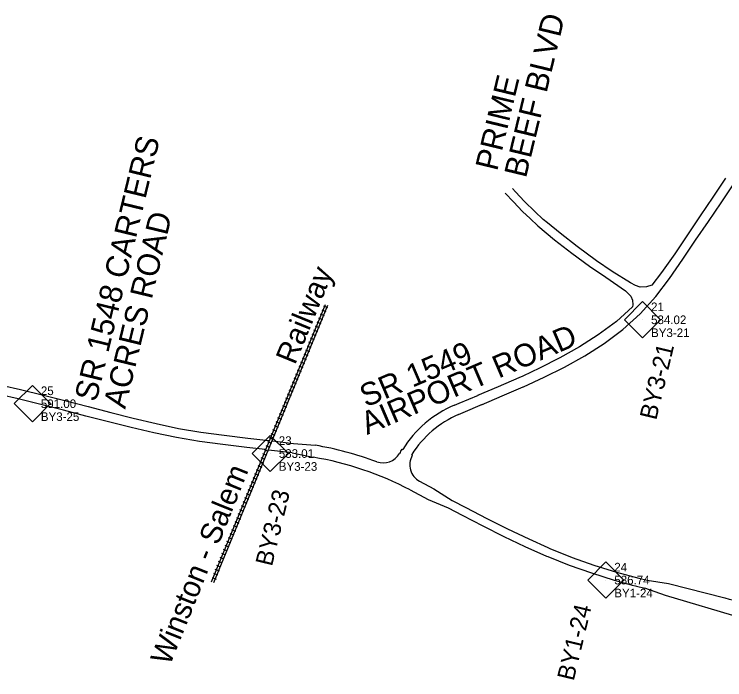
# Model space of a CAD drawing. Extents: x 1649669 to 1659218, y 588594 to 607900.
# Drawn here: x 1653461 to 1655108, y 603379 to 604921 of the extents above; entities that cross this region are included whole.
import ezdxf

# ---------------------------------------------------------------- set-up
doc = ezdxf.new("R2010")
doc.units = 0
for name, color, linetype in [('CTL Supplemental Horizontal and Vertical CELL', 7, 'Continuous'), ('CTL Supplemental Horizontal and Vertical Cogo Comment', 7, 'Continuous'), ('CTL Supplemental Horizontal and Vertical Cogo Elevation', 7, 'Continuous'), ('CTL Supplemental Horizontal and Vertical Cogo Number', 7, 'Continuous'), ('CTL Supplemental Horizontal and Vertical Text', 7, 'Continuous'), ('Default', 7, 'Continuous'), ('Exist Roads EOP', 7, 'Continuous'), ('Old_Level_20', 7, 'Continuous'), ('Prop Paved Shoulder', 7, 'Continuous'), ('Sheet Data Field CELL', 7, 'Continuous')]:
    doc.layers.add(name, color=color, linetype=linetype)

msp = doc.modelspace()

# ---------------------------------------------------------------- linework, layer by layer
at = {"layer": 'CTL Supplemental Horizontal and Vertical CELL'}
for p, q in [((1654917.1, 604213), (1654917.1, 604213)), ((1653502.7, 604018.5), (1653502.7, 604018.5)), ((1654054.2, 603903), (1654054.2, 603903)), ((1654831.9, 603609.7), (1654831.9, 603609.7))]:
    msp.add_line(p, q, dxfattribs=at)
for points in [[(1654875.4, 604213.2), (1654917.3, 604255.1), (1654959.3, 604213.1), (1654917.4, 604171.2)], [(1653461, 604018.7), (1653503, 604060.6), (1653545, 604018.6), (1653503, 603976.6)], [(1654012.4, 603903.2), (1654054.4, 603945.1), (1654096.4, 603903.1), (1654054.4, 603861.2)], [(1654790.2, 603609.9), (1654832.1, 603651.8), (1654874.1, 603609.8), (1654832.2, 603567.9)]]:
    msp.add_lwpolyline(points, close=True, dxfattribs=at)
at = {"layer": 'Default'}
for p, q in [((1653918.1, 603605.5), (1654182.5, 604248.1)), ((1654187.2, 604246.2), (1653922.7, 603603.6)), ((1654187.7, 604240.5), (1654178.5, 604244.3)), ((1654180.1, 604222), (1654170.8, 604225.8)), ((1654183.9, 604231.3), (1654174.6, 604235.1)), ((1654172.5, 604203.5), (1654163.2, 604207.3)), ((1654176.3, 604212.8), (1654167, 604216.6)), ((1654164.9, 604185), (1654155.6, 604188.9)), ((1654168.7, 604194.3), (1654159.4, 604198.1)), ((1654161, 604175.8), (1654151.8, 604179.6)), ((1654153.4, 604157.3), (1654144.2, 604161.1)), ((1654157.2, 604166.6), (1654148, 604170.4)), ((1654145.8, 604138.8), (1654136.6, 604142.6)), ((1654149.6, 604148.1), (1654140.4, 604151.9)), ((1654138.2, 604120.3), (1654129, 604124.1)), ((1654142, 604129.6), (1654132.8, 604133.4)), ((1654134.4, 604111.1), (1654125.1, 604114.9)), ((1654126.8, 604092.6), (1654117.5, 604096.4)), ((1654130.6, 604101.8), (1654121.3, 604105.6)), ((1654119.2, 604074.1), (1654109.9, 604077.9)), ((1654123, 604083.3), (1654113.7, 604087.1)), ((1654111.5, 604055.6), (1654102.3, 604059.4)), ((1654115.3, 604064.8), (1654106.1, 604068.6)), ((1654103.9, 604037.1), (1654094.7, 604040.9)), ((1654107.7, 604046.3), (1654098.5, 604050.2)), ((1654100.1, 604027.9), (1654090.9, 604031.7)), ((1654092.5, 604009.4), (1654083.3, 604013.2)), ((1654096.3, 604018.6), (1654087.1, 604022.4)), ((1654084.9, 603990.9), (1654075.6, 603994.7)), ((1654088.7, 604000.1), (1654079.4, 604003.9)), ((1654077.3, 603972.4), (1654068, 603976.2)), ((1654081.1, 603981.6), (1654071.8, 603985.4)), ((1654073.5, 603963.1), (1654064.2, 603966.9)), ((1654065.8, 603944.6), (1654056.6, 603948.4)), ((1654069.7, 603953.9), (1654060.4, 603957.7)), ((1654058.2, 603926.1), (1654049, 603930)), ((1654062, 603935.4), (1654052.8, 603939.2)), ((1654050.6, 603907.7), (1654041.4, 603911.5)), ((1654054.4, 603916.9), (1654045.2, 603920.7)), ((1654043, 603889.2), (1654033.7, 603893)), ((1654046.8, 603898.4), (1654037.6, 603902.2)), ((1654039.2, 603879.9), (1654029.9, 603883.7)), ((1654031.6, 603861.4), (1654022.3, 603865.2)), ((1654035.4, 603870.7), (1654026.1, 603874.5)), ((1654024, 603842.9), (1654014.7, 603846.7)), ((1654027.8, 603852.2), (1654018.5, 603856)), ((1654016.3, 603824.4), (1654007.1, 603828.2)), ((1654020.1, 603833.7), (1654010.9, 603837.5)), ((1654008.7, 603805.9), (1653999.5, 603809.7)), ((1654012.5, 603815.2), (1654003.3, 603819)), ((1654004.9, 603796.7), (1653995.7, 603800.5)), ((1653997.3, 603778.2), (1653988, 603782)), ((1654001.1, 603787.4), (1653991.9, 603791.3)), ((1653989.7, 603759.7), (1653980.4, 603763.5)), ((1653993.5, 603769), (1653984.2, 603772.8)), ((1653982.1, 603741.2), (1653972.8, 603745)), ((1653985.9, 603750.5), (1653976.6, 603754.3)), ((1653978.3, 603732), (1653969, 603735.8)), ((1653970.6, 603713.5), (1653961.4, 603717.3)), ((1653974.4, 603722.7), (1653965.2, 603726.5)), ((1653963, 603695), (1653953.8, 603698.8)), ((1653966.8, 603704.2), (1653957.6, 603708)), ((1653955.4, 603676.5), (1653946.2, 603680.3)), ((1653959.2, 603685.7), (1653950, 603689.5)), ((1653947.8, 603658), (1653938.5, 603661.8)), ((1653951.6, 603667.2), (1653942.4, 603671.1)), ((1653944, 603648.7), (1653934.7, 603652.6)), ((1653936.4, 603630.3), (1653927.1, 603634.1)), ((1653940.2, 603639.5), (1653930.9, 603643.3)), ((1653919.5, 603615.6), (1653928.7, 603611.8)), ((1653932.6, 603621), (1653923.3, 603624.8))]:
    msp.add_line(p, q, dxfattribs=at)
at = {"layer": 'Exist Roads EOP'}
for p, q in [((1655109.6, 604541.2), (1655080.1, 604497.4)), ((1655099.5, 604484.4), (1655128.7, 604528.2)), ((1654599.1, 604506.1), (1654617.9, 604486.4)), ((1654622.7, 604509.5), (1654615.8, 604517.1)), ((1654643.6, 604486.9), (1654622.7, 604509.5)), ((1654639.3, 604463.6), (1654617.9, 604486.4)), ((1654667.4, 604463.9), (1654643.6, 604486.9)), ((1655080.1, 604497.4), (1655051, 604454)), ((1655070.3, 604441.1), (1655099.5, 604484.4)), ((1654656.7, 604447.4), (1654639.3, 604463.6)), ((1654687.3, 604445.8), (1654667.4, 604463.9)), ((1655051, 604454), (1655021.7, 604410.1)), ((1654674.7, 604431.1), (1654656.7, 604447.4)), ((1654696.9, 604437.9), (1654687.3, 604445.8)), ((1654726.2, 604413.7), (1654696.9, 604437.9)), ((1655040.5, 604397.7), (1655070.3, 604441.1)), ((1654674.7, 604431.1), (1654713.6, 604398.5)), ((1654765.7, 604382.9), (1654726.2, 604413.7)), ((1655021.7, 604410.1), (1655015.1, 604400.3)), ((1654713.6, 604398.5), (1654753.8, 604367.4)), ((1655015.1, 604400.3), (1654992, 604366.1)), ((1655010.5, 604353.3), (1655040.3, 604397.3)), ((1655040.3, 604397.3), (1655040.5, 604397.7)), ((1654810.8, 604349.8), (1654765.7, 604382.9)), ((1654753.8, 604367.4), (1654794.2, 604337.6)), ((1654992, 604366.1), (1654961.4, 604322.5)), ((1654979.9, 604308.9), (1655010.5, 604353.3)), ((1654794.2, 604337.6), (1654832, 604311.6)), ((1654847.3, 604325), (1654810.8, 604349.8)), ((1654889.8, 604298.3), (1654847.3, 604325)), ((1654961.4, 604322.5), (1654938.8, 604292.9)), ((1654832, 604311.6), (1654877.6, 604280.2)), ((1654948.3, 604267), (1654979.9, 604308.9)), ((1654900.7, 604292.5), (1654889.8, 604298.3)), ((1654911.7, 604288.3), (1654900.7, 604292.5)), ((1654926.7, 604289.3), (1654911.7, 604288.3)), ((1654938.8, 604292.9), (1654926.7, 604289.3)), ((1654877.6, 604280.2), (1654881.1, 604276.9)), ((1654881.1, 604276.9), (1654889.9, 604268)), ((1654889.9, 604268), (1654894.1, 604258.6)), ((1654894.1, 604258.6), (1654895.1, 604247.9)), ((1654912.2, 604227), (1654948.3, 604267)), ((1654894.3, 604242.8), (1654856.7, 604208.8)), ((1654895.1, 604247.9), (1654894.3, 604242.8)), ((1654871.7, 604190.8), (1654912.2, 604227)), ((1654856.7, 604208.8), (1654814.8, 604178.1)), ((1654828.4, 604158.2), (1654871.7, 604190.8)), ((1654814.8, 604178.1), (1654770.9, 604150.1)), ((1654783.3, 604129.6), (1654828.4, 604158.2)), ((1654770.9, 604150.1), (1654725.4, 604124.5)), ((1654725.4, 604124.5), (1654678.7, 604101)), ((1654736.6, 604103.4), (1654783.3, 604129.6)), ((1654678.7, 604101), (1654639.7, 604082.7)), ((1654689.1, 604079.8), (1654736.6, 604103.4)), ((1654630.9, 604078.6), (1654582.9, 604057.7)), ((1654639.7, 604082.7), (1654630.9, 604078.6)), ((1654641.4, 604057.9), (1654689.1, 604079.8)), ((1653434.3, 604060.7), (1653475.6, 604051.2)), ((1654582.9, 604057.7), (1654534.8, 604037.6)), ((1654592.1, 604036.6), (1654640.6, 604057.5)), ((1654640.6, 604057.5), (1654641.4, 604057.9)), ((1653475.6, 604051.2), (1653528.7, 604038.4)), ((1653469.8, 604029.9), (1653429.2, 604039.1)), ((1653522.7, 604016.7), (1653469.8, 604029.9)), ((1653528.7, 604038.4), (1653581.3, 604025.1)), ((1653581.3, 604025.1), (1653632.7, 604011.7)), ((1654492.4, 604019.9), (1654537.1, 604038.6)), ((1654543.8, 604016.2), (1654592.1, 604036.6)), ((1653575.2, 604003.5), (1653522.7, 604016.7)), ((1653632.7, 604011.7), (1653684.8, 603998.1)), ((1654481.4, 604015.2), (1654492.4, 604019.9)), ((1654501.8, 603997.8), (1654546.2, 604017.2)), ((1653627.1, 603989.7), (1653575.2, 604003.5)), ((1653684.8, 603998.1), (1653736.9, 603985.1)), ((1654490.8, 603993.2), (1654501.8, 603997.8)), ((1653679.3, 603976.3), (1653627.1, 603989.7)), ((1653731.8, 603963.1), (1653679.3, 603976.3)), ((1653736.9, 603985.1), (1653789.7, 603972.5)), ((1653784.9, 603950.8), (1653731.8, 603963.1)), ((1653789.7, 603972.5), (1653841.5, 603961.4)), ((1653841.5, 603961.4), (1653893.7, 603952.5)), ((1653837.2, 603939.8), (1653784.9, 603950.8)), ((1653893.7, 603952.5), (1653947.8, 603945.4)), ((1653947.8, 603945.4), (1654002.1, 603938.7)), ((1653890.7, 603930.6), (1653837.2, 603939.8)), ((1653944.7, 603923.7), (1653890.7, 603930.6)), ((1654002.1, 603938.7), (1654051.3, 603933)), ((1654059.5, 603932.6), (1654108.4, 603926.3)), ((1654108.4, 603926.3), (1654158.4, 603922.1)), ((1653999.8, 603917.1), (1653944.7, 603923.7)), ((1654042.4, 603912.1), (1653999.8, 603917.1)), ((1654105.3, 603904.5), (1654153.8, 603894.5)), ((1654400.6, 603838.8), (1654433.5, 603821.5)), ((1654379, 603818.6), (1654420.5, 603796.7)), ((1654433.5, 603821.5), (1654475.8, 603794.5)), ((1654420.5, 603796.7), (1654466.5, 603776.9)), ((1654508, 603777.8), (1654556.6, 603752.5)), ((1654499.3, 603760), (1654547.3, 603735.6)), ((1654556.6, 603752.5), (1654604.6, 603728.4)), ((1654547.3, 603735.6), (1654596.2, 603710.8)), ((1654604.6, 603728.4), (1654653.5, 603705.1)), ((1654596.2, 603710.8), (1654644.7, 603687.5)), ((1654653.5, 603705.1), (1654697.8, 603685)), ((1654644.7, 603687.5), (1654695, 603665.1)), ((1654697.8, 603685), (1654702.7, 603682.8)), ((1654702.7, 603682.8), (1654754.5, 603662.2)), ((1654695, 603665.1), (1654697.5, 603664.1)), ((1654697.5, 603664.1), (1654747.5, 603644.3)), ((1654754.5, 603662.2), (1654804.7, 603644.4)), ((1654747.5, 603644.3), (1654798.7, 603626.2)), ((1654804.7, 603644.4), (1654857, 603628.3)), ((1654798.7, 603626.2), (1654851.3, 603609.6)), ((1654851.3, 603609.6), (1654896.5, 603597.4)), ((1654927.8, 603609.4), (1654977.3, 603601.5)), ((1654977.3, 603601.5), (1655108, 603568.3)), ((1654970.5, 603574.3), (1654923, 603590.7)), ((1655180.2, 603512), (1654970.5, 603574.3))]:
    msp.add_line(p, q, dxfattribs=at)
for points in [[(1654105.3, 603904.5), (1654050.4, 603910.6)], [(1654382.6, 603900.8), (1654381.9, 603899.6), (1654383.6, 603898.6)], [(1654475.8, 603794.5), (1654508, 603777.8)], [(1654466.5, 603776.9), (1654499.3, 603760)], [(1654857, 603628.3), (1654908.5, 603614.2), (1654927.8, 603609.4)], [(1654898.1, 603597), (1654903.7, 603595.5), (1654923, 603590.7)]]:
    msp.add_lwpolyline(points, dxfattribs=at)
for centre, radius, start, end in [((1654584.1, 603774.2), 262, 113.0699, 148.1922), ((1654584.1, 603774.2), 238, 113.0699, 147.8583), ((1654031.2, 603158.6), 774, 69.5816, 80.5435), ((1654584.1, 603774.2), 264, 148.1922, 150.7372), ((1654031.2, 603158.6), 746, 62.2176, 80.5435), ((1654316.3, 603924.3), 43, 249.5816, 330.7372), ((1654420.7, 603876.9), 43, 149.7639, 242.2176), ((1656088, 607432), 3986, 255.7673, 256.9954)]:
    msp.add_arc(centre, radius, start, end, dxfattribs=at)
at = {"layer": 'Prop Paved Shoulder'}
msp.add_line((1654359.7, 603913.3), (1654361.4, 603912.3), dxfattribs=at)

# ---------------------------------------------------------------- texts
at = {"layer": 'CTL Supplemental Horizontal and Vertical Cogo Comment'}
for s, p in [('BY3-21', (1654937.1, 604173)), ('BY3-25', (1653522.7, 603978.5)), ('BY3-23', (1654074.2, 603863)), ('BY1-24', (1654851.9, 603569.7))]:
    msp.add_text(s, height=20, dxfattribs=at).set_placement(p)
at = {"layer": 'CTL Supplemental Horizontal and Vertical Cogo Elevation'}
for s, p in [('584.02', (1654937.1, 604203)), ('591.00', (1653522.7, 604008.5)), ('583.01', (1654074.2, 603893)), ('586.74', (1654851.9, 603599.7))]:
    msp.add_text(s, height=20, dxfattribs=at).set_placement(p)
at = {"layer": 'CTL Supplemental Horizontal and Vertical Cogo Number'}
for s, p in [('21', (1654937.1, 604233)), ('25', (1653522.7, 604038.5)), ('23', (1654074.2, 603923)), ('24', (1654851.9, 603629.7))]:
    msp.add_text(s, height=20, dxfattribs=at).set_placement(p)
at = {"layer": 'CTL Supplemental Horizontal and Vertical Text'}
for s, p in [('BY3-21', (1654949, 603978.9)), ('BY3-23', (1654058.4, 603640)), ('BY1-24', (1654757.7, 603374.4))]:
    msp.add_text(s, height=40, rotation=76.4261, dxfattribs=at).set_placement(p)
at = {"layer": 'Old_Level_20'}
for s, rotation, p in [('Railway', 67.6981, (1654111.8, 604106.7)), ('Winston - Salem', 68.0775, (1653821.6, 603409.5))]:
    msp.add_text(s, height=50, rotation=rotation, dxfattribs=at).set_placement(p)
at = {"layer": 'Sheet Data Field CELL'}
for s, height, rotation, p in [('BEEF BLVD', 52.5, 76.4261, (1654647.1, 604539.8)), ('PRIME', 52.5, 76.4261, (1654580.2, 604556)), ('SR 1548 CARTERS', 52.501, 76.4261, (1653651.3, 604020.9)), ('ACRES ROAD', 52.5, 76.4261, (1653718.2, 604004.7)), ('AIRPORT ROAD', 52.501, 23.2022, (1654279, 603945.9)), ('SR 1549', 52.5, 23.0531, (1654276.1, 604009.5))]:
    msp.add_text(s, height=height, rotation=rotation, dxfattribs=at).set_placement(p)

doc.saveas('drawing.dxf')
